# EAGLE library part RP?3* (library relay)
Power PCB Relay RP II/1 SCHRACK 1 pole 16 A Source: http://www.schrack.com/.. 5834.pdf
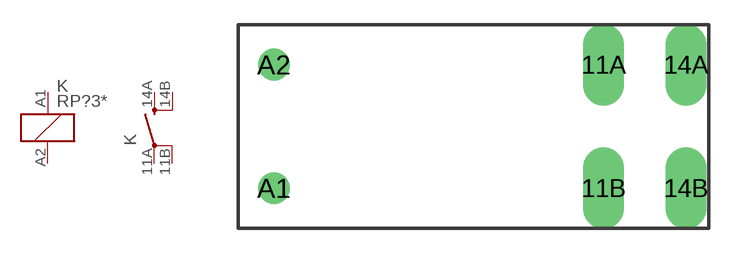
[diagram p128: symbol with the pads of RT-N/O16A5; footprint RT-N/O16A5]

Designator prefix K; gates 1=K 2=S-X2

## RP33 (MPN: RP330048; OC_FARNELL: 388178; OC_NEWARK: 48M7779)  [RT-N/O16A5]
11A  2:PA  pas
11B  2:PB  pas
14A  2:SA  pas
14B  2:SB  pas
A1  1:1  pas
A2  1:2  pas

## RP730005 (OC_FARNELL: unknown; OC_NEWARK: unknown), RP730006 (OC_FARNELL: unknown; OC_NEWARK: unknown), RP730012 (OC_FARNELL: unknown; OC_NEWARK: unknown), RP730024 (OC_FARNELL: unknown; OC_NEWARK: unknown), RP730048 (OC_FARNELL: unknown; OC_NEWARK: unknown), RP730060 (OC_FARNELL: unknown; OC_NEWARK: unknown), RP730110 (OC_FARNELL: unknown; OC_NEWARK: unknown)  [RT-N/O16A5]
Pads as for RT-N/O16A5

## Footprint RT-N/O16A5 (pad centres in mm)
Power PCB Relay 1 pole 12 / 16 A, DC- or AC-coil SCHRACK 16 A, pinning 5mm Source: http://www.schrack.com/.. 5819.pdf
drill 1.3 pad 2.5 long: 11A 7.56,3.78; 11B 7.56,-3.78; 14A 12.6,3.78; 14B 12.6,-3.78
drill 1.3 round: A1 -12.6,-3.78; A2 -12.6,3.78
